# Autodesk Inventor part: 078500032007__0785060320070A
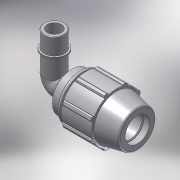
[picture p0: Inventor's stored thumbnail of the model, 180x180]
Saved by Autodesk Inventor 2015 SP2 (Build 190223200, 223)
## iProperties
Created: 2017-02
Part Number: 078500032007__0785060320070A
Material: PVC-Piping
Description: PLASSON 90° ELBOW MALE ADAPTOR 32-3/4"
Document SubType Name: Modeling
Designer: KIM
Mass: 92.6774 g
Surface Area: 199.44 cm^2
Volume: 66.1981 cm^3
Density: 1.4 g/cm^3
Appearance: Smooth - White
Author: KIM
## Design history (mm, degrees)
derived "07850.ipt"
feature "Solid1::07850.ipt"
tag "TaggingFeature1"
body "Solid1"
other parameters: "d2" = 32, "d4" = 8.66667, "d5" = 26, "d7" = 64, "d9" = 14.85714, "d11" = 3.46667, "d13" = 120 deg, "d14" = 44.8, "d15" = 12 deg, "d16" = 55.68, "d18" = 1.6, "d19" = 35 deg, "d20" = 17.5 deg, "d21" = 59.52, "d23" = 0, "d25" = 360 deg, "d27" = 1.28, "d33" = 0.64, "d42" = 38.48, "d43" = 1.92, "d46" = 0.96, "d51" = 104, "d68" = 3.46667, "d72" = 55, "d73" = 26.441, "d74" = 18, "d75" = 30.40715, "d76" = 18.5087, "d77" = 19.8, "d79" = 10.5764, "d80" = 0.79323, "d83" = 0, "d84" = 0, "d91" = 48, "d93" = 67, "d94" = 26.441, "d95" = 18.5087, "d96" = 10.4, "d97" = 50 deg, "d_" = 32, "E_" = 64, "A_" = 104, "l_" = 67, "l_2" = 18, "A_1" = 55, "R_" = 26.441
